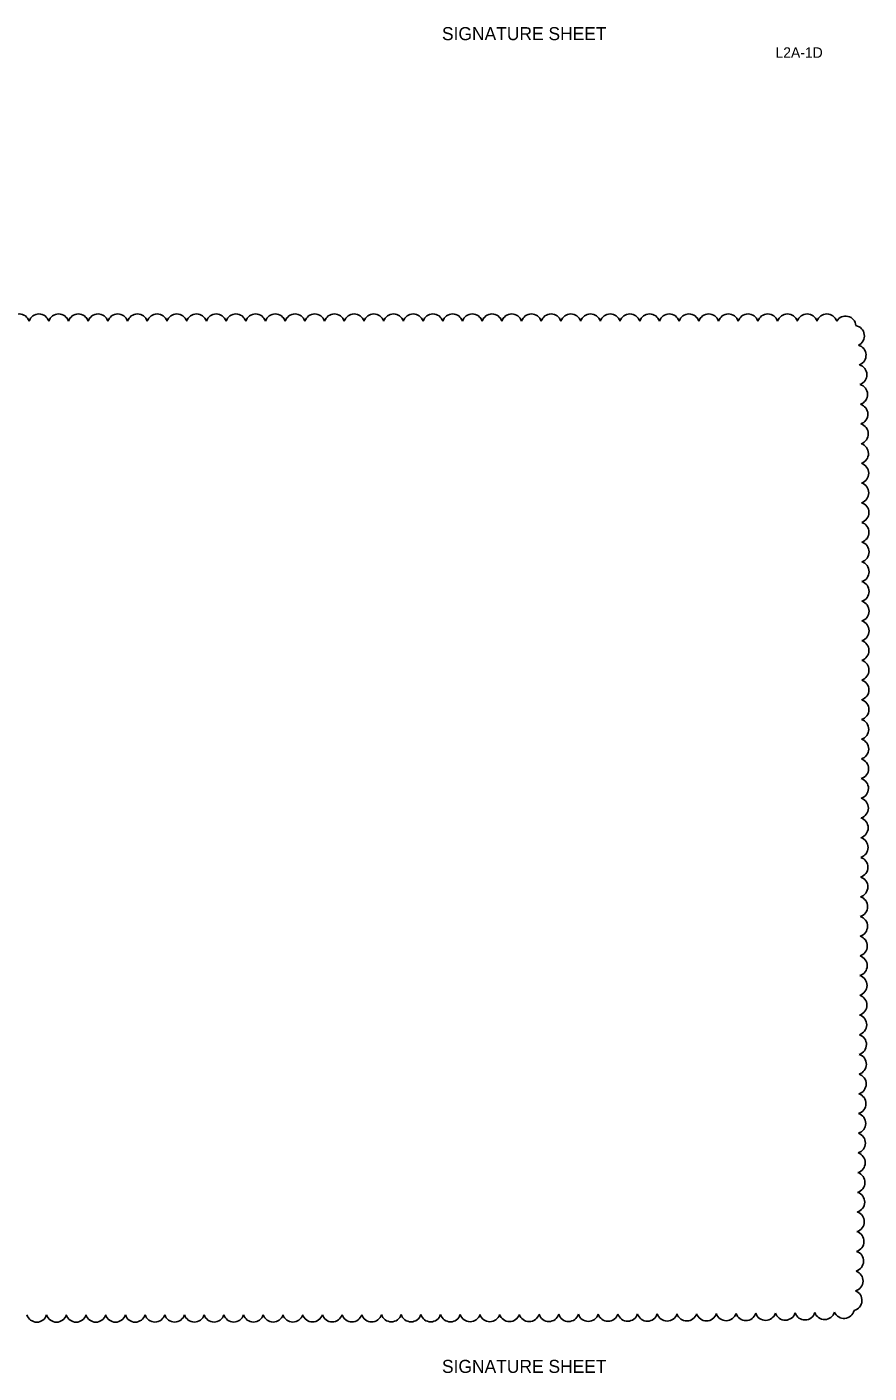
# Model space of a CAD drawing. Extents: x -811 to 10319, y -2309 to 9962.
# Drawn here: x -803.18 to -795.1, y -2257.92 to -2245.01 of the extents above; entities that cross this region are included whole.
import ezdxf

# ---------------------------------------------------------------- set-up
doc = ezdxf.new("R2010")
doc.units = 0
for name, color, linetype in [('PlotBorder_dp', 7, 'Continuous'), ('ScratchEle_dp', 7, 'Continuous'), ('SheetLines_dp', 7, 'Continuous')]:
    doc.layers.add(name, color=color, linetype=linetype)

msp = doc.modelspace()

# ---------------------------------------------------------------- linework, layer by layer
at = {"layer": 'ScratchEle_dp'}
for centre, radius, start, end in [((-803.255, -2247.864), 0.0991, 17.5008, 162.5008), ((-803.066, -2247.864), 0.0991, 17.5, 162.5), ((-802.877, -2247.864), 0.0991, 17.5, 162.5), ((-802.688, -2247.864), 0.0991, 17.5, 162.5), ((-802.499, -2247.864), 0.0991, 17.5, 162.5), ((-802.31, -2247.864), 0.0991, 17.5, 162.5), ((-802.121, -2247.864), 0.0991, 17.5, 162.5), ((-801.932, -2247.864), 0.0991, 17.5, 162.5), ((-801.743, -2247.864), 0.0991, 17.5, 162.5), ((-801.554, -2247.864), 0.0991, 17.5, 162.5), ((-801.365, -2247.864), 0.0991, 17.5, 162.5), ((-801.176, -2247.864), 0.0991, 17.5, 162.5), ((-800.987, -2247.864), 0.0991, 17.5, 162.5), ((-800.798, -2247.864), 0.0991, 17.5, 162.5), ((-800.609, -2247.864), 0.0991, 17.5, 162.5), ((-800.42, -2247.864), 0.0991, 17.5, 162.5), ((-800.231, -2247.864), 0.0991, 17.5, 162.5), ((-800.042, -2247.864), 0.0991, 17.5, 162.5), ((-799.853, -2247.864), 0.0991, 17.5, 162.5), ((-799.664, -2247.864), 0.0991, 17.5, 162.5), ((-799.475, -2247.864), 0.0991, 17.5, 162.5), ((-799.286, -2247.864), 0.0991, 17.5, 162.5), ((-799.097, -2247.864), 0.0991, 17.5, 162.5), ((-798.908, -2247.864), 0.0991, 17.5, 162.5), ((-798.719, -2247.864), 0.0991, 17.5, 162.5), ((-798.53, -2247.864), 0.0991, 17.5, 162.5), ((-798.341, -2247.864), 0.0991, 17.5, 162.5), ((-798.152, -2247.864), 0.0991, 17.5, 162.5), ((-797.963, -2247.864), 0.0991, 17.5, 162.5), ((-797.774, -2247.864), 0.0991, 17.5, 162.5), ((-797.585, -2247.864), 0.0991, 17.5, 162.5), ((-797.396, -2247.864), 0.0991, 17.5, 162.5), ((-797.207, -2247.864), 0.0991, 17.5, 162.5), ((-797.018, -2247.864), 0.0991, 17.5, 162.5), ((-796.829, -2247.864), 0.0991, 17.5, 162.5), ((-796.64, -2247.864), 0.0991, 17.5, 162.5), ((-796.451, -2247.864), 0.0991, 17.5, 162.5), ((-796.262, -2247.864), 0.0991, 17.5, 162.5), ((-796.073, -2247.864), 0.0991, 17.5, 162.5), ((-795.884, -2247.864), 0.0991, 17.5, 162.5), ((-795.695, -2247.864), 0.0991, 17.5, 162.5), ((-795.506, -2247.864), 0.0991, 17.5, 162.5), ((-795.326, -2247.884), 0.099, 4.4162, 149.4162), ((-795.245, -2247.974), 0.0992, 294.7802, 79.7802), ((-795.229, -2248.16), 0.0991, 290.3649, 75.3649), ((-795.221, -2248.348), 0.0991, 289.3839, 74.3839), ((-795.215, -2248.537), 0.0991, 288.8712, 73.8712), ((-795.212, -2248.726), 0.0991, 288.5423, 73.5423), ((-795.208, -2248.915), 0.0991, 288.3081, 73.3081), ((-795.206, -2249.104), 0.0991, 288.1304, 73.1304), ((-795.204, -2249.292), 0.0991, 287.9896, 72.9896), ((-795.203, -2249.481), 0.0991, 287.8744, 72.8744), ((-795.202, -2249.67), 0.0991, 287.778, 72.778), ((-795.201, -2249.859), 0.0991, 287.6956, 72.6956), ((-795.2, -2250.048), 0.0991, 287.6243, 72.6243), ((-795.2, -2250.237), 0.0991, 287.5617, 72.5617), ((-795.2, -2250.426), 0.0991, 287.5062, 72.5062), ((-795.2, -2250.615), 0.0991, 287.4565, 72.4565), ((-795.2, -2250.804), 0.0991, 287.4117, 72.4117), ((-795.201, -2250.993), 0.0991, 287.3711, 72.3711), ((-795.201, -2251.182), 0.0991, 287.3339, 72.3339), ((-795.202, -2251.371), 0.0991, 287.2999, 72.2999), ((-795.202, -2251.56), 0.0991, 287.2684, 72.2684), ((-795.203, -2251.749), 0.0991, 287.2394, 72.2394), ((-795.204, -2251.938), 0.0991, 287.2123, 72.2123), ((-795.205, -2252.127), 0.0991, 287.1871, 72.1871), ((-795.206, -2252.316), 0.0991, 287.1635, 72.1635), ((-795.207, -2252.505), 0.0991, 287.1414, 72.1414), ((-795.209, -2252.694), 0.0991, 287.126, 72.126), ((-795.21, -2252.883), 0.0991, 287.1162, 72.1162), ((-795.211, -2253.072), 0.0991, 287.1058, 72.1058), ((-795.212, -2253.261), 0.0991, 287.0946, 72.0946), ((-795.214, -2253.45), 0.0991, 287.0827, 72.0827), ((-795.215, -2253.639), 0.0991, 287.0698, 72.0698), ((-795.217, -2253.828), 0.0991, 287.0559, 72.0559), ((-795.218, -2254.017), 0.0991, 287.0408, 72.0408), ((-795.22, -2254.206), 0.0991, 287.0244, 72.0244), ((-795.221, -2254.395), 0.0991, 287.0064, 72.0064), ((-795.223, -2254.584), 0.0991, 286.9865, 71.9865), ((-795.225, -2254.773), 0.0991, 286.9645, 71.9645), ((-795.226, -2254.962), 0.0991, 286.94, 71.94), ((-795.228, -2255.151), 0.0991, 286.9123, 71.9123), ((-795.23, -2255.34), 0.0991, 286.8807, 71.8807), ((-795.232, -2255.529), 0.0991, 286.8443, 71.8443), ((-795.235, -2255.718), 0.0991, 286.8016, 71.8016), ((-795.237, -2255.907), 0.0991, 286.7507, 71.7507), ((-795.24, -2256.096), 0.0991, 286.6884, 71.6884), ((-795.242, -2256.285), 0.0991, 286.6098, 71.6098), ((-795.246, -2256.473), 0.0991, 286.5063, 71.5063), ((-795.249, -2256.662), 0.0991, 286.3609, 71.3609), ((-795.253, -2256.851), 0.0991, 286.1344, 71.1344), ((-795.258, -2257.04), 0.0991, 285.7012, 70.7012), ((-795.268, -2257.228), 0.099, 283.7418, 68.7418), ((-803.087, -2257.337), 0.0991, 197.4952, 342.4952), ((-802.898, -2257.337), 0.0991, 197.5007, 342.5007), ((-802.709, -2257.337), 0.0991, 197.5043, 342.5043), ((-802.52, -2257.337), 0.0991, 197.5079, 342.5079), ((-802.331, -2257.337), 0.0991, 197.5117, 342.5117), ((-802.142, -2257.337), 0.0991, 197.5156, 342.5156), ((-801.953, -2257.336), 0.0991, 197.5197, 342.5197), ((-801.764, -2257.336), 0.0991, 197.5239, 342.5239), ((-801.575, -2257.336), 0.0991, 197.5284, 342.5284), ((-801.386, -2257.336), 0.0991, 197.533, 342.533), ((-801.197, -2257.336), 0.0991, 197.5379, 342.5379), ((-801.008, -2257.336), 0.0991, 197.543, 342.543), ((-800.819, -2257.336), 0.0991, 197.5483, 342.5483), ((-800.63, -2257.336), 0.0991, 197.554, 342.554), ((-800.441, -2257.335), 0.0991, 197.5599, 342.5599), ((-800.252, -2257.335), 0.0991, 197.5662, 342.5662), ((-800.063, -2257.335), 0.0991, 197.5729, 342.5729), ((-799.874, -2257.335), 0.0991, 197.5799, 342.5799), ((-799.685, -2257.334), 0.0991, 197.5874, 342.5874), ((-799.496, -2257.334), 0.0991, 197.5954, 342.5954), ((-799.307, -2257.334), 0.0991, 197.604, 342.604), ((-799.118, -2257.334), 0.0991, 197.6131, 342.6131), ((-798.929, -2257.333), 0.0991, 197.623, 342.623), ((-798.74, -2257.333), 0.0991, 197.6337, 342.6337), ((-798.551, -2257.332), 0.0991, 197.6452, 342.6452), ((-798.362, -2257.332), 0.0991, 197.6578, 342.6578), ((-798.173, -2257.331), 0.0991, 197.6716, 342.6716), ((-797.984, -2257.331), 0.0991, 197.6868, 342.6868), ((-797.795, -2257.33), 0.0991, 197.7037, 342.7037), ((-797.606, -2257.329), 0.0991, 197.7225, 342.7225), ((-797.417, -2257.328), 0.0991, 197.7438, 342.7438), ((-797.228, -2257.328), 0.0991, 197.768, 342.768), ((-797.039, -2257.327), 0.0991, 197.796, 342.796), ((-796.85, -2257.326), 0.0991, 197.8288, 342.8288), ((-796.661, -2257.325), 0.0991, 197.8681, 342.8681), ((-796.472, -2257.323), 0.0991, 197.9161, 342.9161), ((-796.283, -2257.322), 0.0991, 197.9767, 342.9767), ((-796.094, -2257.32), 0.0991, 198.0568, 343.0568), ((-795.905, -2257.318), 0.0991, 198.1697, 343.1697), ((-795.716, -2257.316), 0.0991, 198.3466, 343.3466), ((-795.528, -2257.312), 0.0991, 198.6898, 343.6898), ((-795.341, -2257.302), 0.0992, 202.4244, 347.4244)]:
    msp.add_arc(centre, radius, start, end, dxfattribs=at)

# ---------------------------------------------------------------- texts
at = {"layer": 'PlotBorder_dp'}
for p in [(-799.524, -2245.138), (-799.524, -2257.923)]:
    msp.add_text('       SIGNATURE SHEET         ', height=0.125, dxfattribs=at).set_placement(p)
at = {"layer": 'SheetLines_dp'}
msp.add_text('L2A-1D', height=0.1, dxfattribs=at).set_placement((-795.999, -2245.307))

doc.saveas('drawing.dxf')
